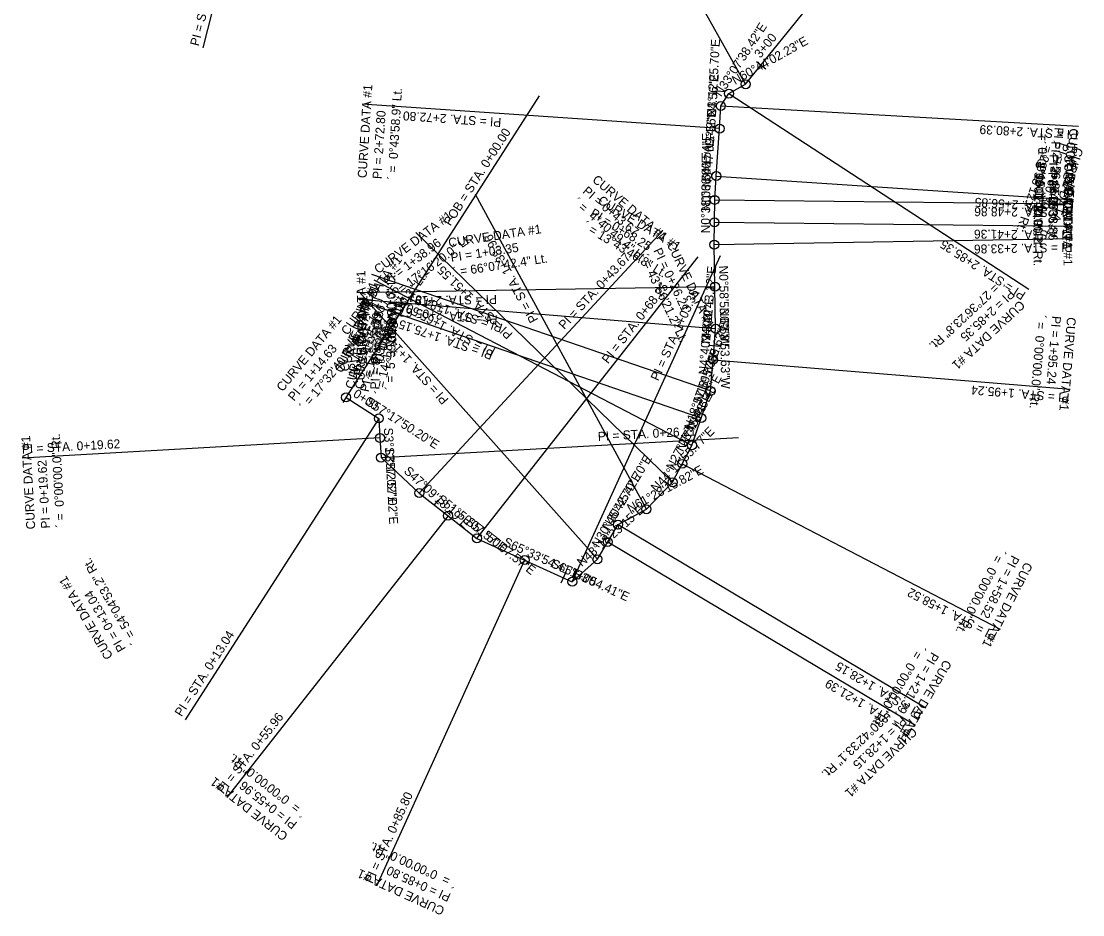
# Model space of a CAD drawing. Extents: x 1158784 to 1165006, y 610007 to 611539.
# Drawn here: x 1163730.4 to 1164086.1, y 610007.4 to 610306.8 of the extents above; entities that cross this region are included whole.
import ezdxf

# ---------------------------------------------------------------- set-up
doc = ezdxf.new("R2010")
doc.units = 0
for name, color, linetype in [('D_Roadway_Centerline', 7, 'Continuous'), ('D_Roadway_Centerline_Bearings', 7, 'Continuous'), ('D_Roadway_Centerline_CurveData', 7, 'Continuous'), ('D_Roadway_Centerline_Flags', 7, 'Continuous'), ('D_Roadway_Centerline_Text', 7, 'Continuous')]:
    doc.layers.add(name, color=color, linetype=linetype)

msp = doc.modelspace()

# ---------------------------------------------------------------- linework, layer by layer
at = {"layer": 'D_Roadway_Centerline'}
for p, q in [((1163973.13, 610285.71), (1164038.5, 610366.61)), ((1163967.54, 610282.58), (1163973.13, 610285.71)), ((1163964.82, 610278.42), (1163967.54, 610282.58)), ((1163964.4, 610270.84), (1163964.82, 610278.42)), ((1163963.3, 610254.93), (1163964.4, 610270.84)), ((1163962.77, 610246.96), (1163963.3, 610254.93)), ((1163962.69, 610239.46), (1163962.77, 610246.96)), ((1163962.61, 610231.96), (1163962.69, 610239.46)), ((1163962.85, 610217.87), (1163962.61, 610231.96)), ((1163963.09, 610203.78), (1163962.85, 610217.87)), ((1163962.24, 610193.38), (1163963.09, 610203.78)), ((1163961.39, 610182.98), (1163962.24, 610193.38)), ((1163958.25, 610173.85), (1163961.39, 610182.98)), ((1163839.27, 610180.8), (1163850.24, 610173.76)), ((1163850.24, 610173.76), (1163850.61, 610167.18)), ((1163955.12, 610164.72), (1163958.25, 610173.85)), ((1163850.61, 610167.18), (1163850.98, 610160.61)), ((1163951.9, 610158.53), (1163955.12, 610164.72)), ((1163850.98, 610160.61), (1163863.78, 610148.74)), ((1163948.68, 610152.34), (1163951.9, 610158.53)), ((1163939.9, 610143.31), (1163948.68, 610152.34)), ((1163863.78, 610148.74), (1163873.45, 610141.14)), ((1163930.41, 610138.15), (1163939.9, 610143.31)), ((1163873.45, 610141.14), (1163883.11, 610133.55)), ((1163926.95, 610132.35), (1163930.41, 610138.15)), ((1163883.11, 610133.55), (1163899.09, 610126.29)), ((1163923.49, 610126.54), (1163926.95, 610132.35)), ((1163899.09, 610126.29), (1163915.06, 610119.03)), ((1163915.06, 610119.03), (1163923.49, 610126.54))]:
    msp.add_line(p, q, dxfattribs=at)
at = {"layer": 'D_Roadway_Centerline_Flags'}
for points in [[(1163820.82, 610414.26), (1163791.31, 610297.95)], [(1163973.13, 610285.71), (1163914.47, 610390.4)], [(1163839.27, 610180.8), (1163904.11, 610281.78)], [(1163967.54, 610282.58), (1164068.03, 610217)], [(1163964.4, 610270.84), (1163844.68, 610279.08)], [(1163964.82, 610278.42), (1164084.63, 610271.7)], [(1163963.3, 610254.93), (1164083.04, 610247.01)], [(1163939.9, 610143.31), (1163882.59, 610248.74)], [(1163962.77, 610246.96), (1164082.77, 610245.63)], [(1163962.69, 610239.46), (1164082.68, 610238.13)], [(1163948.68, 610152.34), (1163862.64, 610236)], [(1163863.78, 610148.74), (1163945.38, 610236.72)], [(1163962.61, 610231.96), (1164082.59, 610234.02)], [(1163883.11, 610133.55), (1163957.26, 610227.9)], [(1163915.06, 610119.03), (1163964.7, 610228.28)], [(1163961.39, 610182.98), (1163847.9, 610221.98)], [(1163962.85, 610217.87), (1163842.87, 610215.81)], [(1163955.12, 610164.72), (1163848.65, 610220.09)], [(1163963.09, 610203.78), (1163843.49, 610213.56)], [(1163923.49, 610126.54), (1163843.67, 610216.14)], [(1163958.25, 610173.85), (1163844.77, 610212.85)], [(1163962.24, 610193.38), (1164081.84, 610183.59)], [(1163850.24, 610173.76), (1163785.41, 610072.78)], [(1163850.61, 610167.18), (1163730.8, 610160.45)], [(1163850.98, 610160.61), (1163970.79, 610167.34)], [(1163951.9, 610158.53), (1164058.36, 610103.16)], [(1163873.45, 610141.14), (1163799.29, 610046.79)], [(1163930.41, 610138.15), (1164033.52, 610076.78)], [(1163926.95, 610132.35), (1164030.07, 610070.97)], [(1163899.09, 610126.29), (1163849.45, 610017.04)]]:
    msp.add_lwpolyline(points, dxfattribs=at)
for centre in [(1163973.13, 610285.71), (1163967.54, 610282.58), (1163964.82, 610278.42), (1163964.4, 610270.84), (1163963.3, 610254.93), (1163962.77, 610246.96), (1163962.69, 610239.46), (1163962.61, 610231.96), (1163962.85, 610217.87), (1163963.09, 610203.78), (1163962.24, 610193.38), (1163839.27, 610180.8), (1163961.39, 610182.98), (1163850.24, 610173.76), (1163958.25, 610173.85), (1163850.61, 610167.18), (1163955.12, 610164.72), (1163850.98, 610160.61), (1163951.9, 610158.53), (1163948.68, 610152.34), (1163863.78, 610148.74), (1163873.45, 610141.14), (1163939.9, 610143.31), (1163930.41, 610138.15), (1163883.11, 610133.55), (1163926.95, 610132.35), (1163899.09, 610126.29), (1163923.49, 610126.54), (1163915.06, 610119.03)]:
    msp.add_circle(centre, 1.5, dxfattribs=at)
at = {"layer": 'D_Roadway_Centerline_Text'}
for points in [[(1163976.75, 610293.37), (1163979.86, 610290.86)], [(1163960.85, 610248.23), (1163962.85, 610248.09)], [(1163960.64, 610198.28), (1163964.62, 610197.96)], [(1163840.35, 610182.49), (1163838.19, 610179.12)], [(1163946.16, 610152.63), (1163947.6, 610151.23)], [(1163870, 610146.4), (1163868.76, 610144.82)], [(1163912.85, 610122.23), (1163911.19, 610118.59)]]:
    msp.add_lwpolyline(points, dxfattribs=at)

# ---------------------------------------------------------------- texts
at = {"layer": 'D_Roadway_Centerline_Bearings'}
for s, rotation, p in [('N33%%d07\'38.42"E', 56.8727, (1163964.92, 610281.32)), ('N3%%d12\'25.70"E', 86.7929, (1163963.11, 610274.71)), ('N60%%d44\'02.23"E', 29.266, (1163969.6, 610285.45)), ('N3%%d56\'24.56"E', 86.0598, (1163962.35, 610262.99)), ('N3%%d47\'09.42"E', 86.214, (1163961.54, 610251.04)), ('N0%%d38\'06.54"E', 89.3648, (1163961.23, 610243.23)), ('N0%%d38\'06.54"E', 89.3648, (1163961.15, 610235.73)), ('N4%%d40\'43.12"E', 85.3214, (1163961.17, 610198.7)), ('N0%%d58\'53.63"W', 270.9816, (1163964.23, 610224.94)), ('N4%%d40\'43.12"E', 85.3214, (1163960.32, 610188.3)), ('N0%%d58\'53.63"W', 270.9816, (1163964.47, 610210.85)), ('N18%%d57\'59.63"E', 71.0334, (1163958.4, 610178.9)), ('N18%%d57\'59.63"E', 71.0334, (1163955.27, 610169.77)), ('N27%%d28\'45.48"E', 62.5207, (1163952.17, 610162.32)), ('N27%%d28\'45.48"E', 62.5207, (1163948.95, 610156.13)), ('S57%%d17\'50.20"E', 327.2973, (1163845.57, 610178.54)), ('S3%%d12\'57.02"E', 273.2158, (1163851.93, 610170.55)), ('N44%%d11\'55.77"E', 45.8012, (1163943.21, 610148.87)), ('S3%%d12\'57.02"E', 273.2158, (1163852.3, 610163.98)), ('N30%%d45\'42.70"E', 59.2381, (1163927.39, 610136.02)), ('S47%%d09\'18.19"E', 317.1551, (1163858.4, 610155.77)), ('N61%%d28\'15.82"E', 28.5289, (1163934.44, 610142.05)), ('N30%%d45\'42.70"E', 59.2381, (1163923.93, 610130.21)), ('S51%%d50\'07.57"E', 321.8354, (1163869.54, 610146.12)), ('N48%%d18\'23.15"E', 41.6936, (1163918.28, 610123.9)), ('S51%%d50\'07.57"E', 321.8354, (1163879.2, 610138.52)), ('S65%%d33\'54.41"E', 335.5651, (1163891.72, 610131.28)), ('S65%%d33\'54.41"E', 335.5651, (1163907.7, 610124.02))]:
    msp.add_text(s, height=3, rotation=rotation, dxfattribs=at).set_placement(p)
at = {"layer": 'D_Roadway_Centerline_CurveData'}
for s, rotation, p in [('CURVE DATA #1', 86.4264, (1163846.13, 610254.18)), ('´ =  0%%d43\'58.9" Lt.', 86.4264, (1163856.11, 610253.56)), ('PI = 2+72.80', 86.4264, (1163851.12, 610253.87)), ('´ =  0%%d09\'15.1" Rt.', 266.1369, (1164071.68, 610271.67)), ('PI = 2+56.85', 266.1369, (1164076.66, 610271.33)), ('CURVE DATA #1', 266.1369, (1164081.65, 610271)), ('´ = 29%%d55\'12.7" Rt.', 251.8328, (1164073.97, 610267.86)), ('´ =  3%%d09\'02.9" Rt.', 267.7894, (1164070.62, 610266.81)), ('PI = 2+80.39', 251.8328, (1164078.72, 610266.3)), ('CURVE DATA #1', 251.8328, (1164083.47, 610264.74)), ('PI = 2+48.86', 267.7894, (1164075.62, 610266.62)), ('CURVE DATA #1', 267.7894, (1164080.61, 610266.43)), ('´ =  0%%d00\'00.0" Rt.', 269.3648, (1164069.95, 610262.27)), ('PI = 2+41.36', 269.3648, (1164074.95, 610262.22)), ('CURVE DATA #1', 269.3648, (1164079.95, 610262.16)), ('´ =  1%%d37\'00.2" Rt.', 270.1732, (1164069.54, 610256.29)), ('PI = 2+33.86', 270.1732, (1164074.54, 610256.3)), ('CURVE DATA #1', 270.1732, (1164079.54, 610256.32)), ('CURVE DATA #1', 319.4952, (1163921.53, 610253.29)), ('PI = 0+43.67', 319.4952, (1163918.28, 610249.48)), ('´ =  4%%d40\'49.4" Lt.', 319.4952, (1163915.03, 610245.68)), ('CURVE DATA #1', 328.7003, (1163923.38, 610245.99)), ('CURVE DATA #1', 37.1651, (1163850.09, 610222.05)), ('PI = 0+68.25', 328.7003, (1163920.79, 610241.72)), ('CURVE DATA #1', 8.6293, (1163873.78, 610231.1)), ('´ = 13%%d43\'46.8" Lt.', 328.7003, (1163918.19, 610237.44)), ('´ = 17%%d16\'20.0" Lt.', 37.1651, (1163856.13, 610214.08)), ('PI = 1+38.96', 37.1651, (1163853.11, 610218.07)), ('PI = 1+03.35', 8.6293, (1163874.53, 610226.16)), ('PI = 0+26.21', 295.1854, (1163942.12, 610229.99)), ('CURVE DATA #1', 295.1854, (1163946.65, 610232.11)), ('CURVE DATA #1', 54.1609, (1163839.78, 610201.39)), ('´ = 66%%d07\'42.4" Lt.', 8.6293, (1163875.28, 610221.22)), ('´ = 43%%d56\'21.2" Lt.', 295.1854, (1163937.6, 610227.86)), ('CURVE DATA #1', 90.9816, (1163846.28, 610191.87)), ('´ = 16%%d43\'10.3" Lt.', 54.1609, (1163847.88, 610195.53)), ('´ =  0%%d00\'00.0" Lt.', 90.9816, (1163856.28, 610192.04)), ('CURVE DATA #1', 66.7771, (1163838.13, 610188.8)), ('CURVE DATA #1', 71.0334, (1163839.8, 610189.18)), ('PI = 1+51.55', 54.1609, (1163843.83, 610198.46)), ('´ = 27%%d36\'23.8" Rt.', 223.0694, (1164058.14, 610220.8)), ('PI = 2+85.35', 223.0694, (1164061.55, 610217.15)), ('CURVE DATA #1', 78.1774, (1163841.95, 610183.46)), ('CURVE DATA #1', 88.1515, (1163845.38, 610183.56)), ('´ =  8%%d30\'45.9" Lt.', 66.7771, (1163847.32, 610184.86)), ('´ =  0%%d00\'00.0" Lt.', 71.0334, (1163849.26, 610185.93)), ('PI = 2+19.77', 90.9816, (1163851.28, 610191.95)), ('´ =  5%%d39\'36.8" Lt.', 88.1515, (1163855.37, 610183.24)), ('PI = 1+75.15', 71.0334, (1163844.53, 610187.55)), ('´ = 14%%d17\'16.5" Lt.', 78.1774, (1163851.74, 610181.41)), ('CURVE DATA #1', 223.0694, (1164064.97, 610213.49)), ('CURVE DATA #1', 50.4659, (1163817.98, 610182.5)), ('PI = 1+65.50', 66.7771, (1163842.73, 610186.83)), ('PI = 2+05.67', 88.1515, (1163850.38, 610183.4)), ('´ =  0%%d00\'00.0" Rt.', 265.3214, (1164070.84, 610208.57)), ('PI = 1+95.24', 265.3214, (1164075.82, 610208.16)), ('CURVE DATA #1', 265.3214, (1164080.81, 610207.75)), ('PI = 1+84.81', 78.1774, (1163846.85, 610182.43)), ('´ = 17%%d32\'40.5" Lt.', 50.4659, (1163825.69, 610176.14)), ('PI = 1+14.63', 50.4659, (1163821.84, 610179.32)), ('CURVE DATA #1', 93.2158, (1163735.15, 610136.66)), ('´ =  0%%d00\'00.0" Rt.', 93.2158, (1163745.13, 610137.22)), ('PI = 0+19.62', 93.2158, (1163740.14, 610136.94)), ('´ =  0%%d00\'00.0" Rt.', 242.5207, (1164057.9, 610130.45)), ('PI = 1+58.52', 242.5207, (1164062.33, 610128.14)), ('´ = 54%%d04\'53.2" Rt.', 120.2566, (1163769.91, 610099.11)), ('CURVE DATA #1', 242.5207, (1164066.77, 610125.84)), ('CURVE DATA #1', 120.2566, (1163761.28, 610094.07)), ('PI = 0+13.04', 120.2566, (1163765.59, 610096.59)), ('´ =  0%%d00\'00.0" Rt.', 239.2381, (1164031.17, 610098.24)), ('CURVE DATA #1', 239.2381, (1164039.76, 610093.13)), ('PI = 1+21.39', 239.2381, (1164035.47, 610095.68)), ('´ = 30%%d42\'33.1" Rt.', 223.8835, (1164021.88, 610077.67)), ('PI = 1+28.15', 223.8835, (1164025.34, 610074.07)), ('CURVE DATA #1', 223.8835, (1164028.81, 610070.46)), ('´ =  0%%d00\'00.0" Rt.', 141.8354, (1163826.2, 610042.18)), ('CURVE DATA #1', 141.8354, (1163820.02, 610034.32)), ('PI = 0+55.96', 141.8354, (1163823.11, 610038.25)), ('´ =  0%%d00\'00.0" Rt.', 155.5651, (1163876.67, 610018.94)), ('CURVE DATA #1', 155.5651, (1163872.54, 610009.84)), ('PI = 0+85.80', 155.5651, (1163874.61, 610014.39))]:
    msp.add_text(s, height=3, rotation=rotation, dxfattribs=at).set_placement(p)
at = {"layer": 'D_Roadway_Centerline_Flags'}
for s, rotation, p in [('PI = STA. 7+03.19', 75.7635, (1163789.86, 610298.31)), ('PI = STA. 2+72.80', 176.0598, (1163891.37, 610274.37)), ('POB = STA. 0+00.00', 57.2973, (1163874.22, 610238.01)), ('PI = STA. 2+80.39', 176.7929, (1164084.55, 610270.21)), ('PI = STA. 2+56.85', 176.214, (1164082.94, 610245.51)), ('PI = STA. 2+48.86', 179.3648, (1164082.75, 610244.13)), ('PI = STA. 1+38.96', 118.5289, (1163903.7, 610206.77)), ('PI = STA. 2+41.36', 179.3648, (1164082.67, 610236.63)), ('PI = STA. 2+85.35', 146.8727, (1164067.21, 610215.74)), ('PI = STA. 2+33.86', 180.9816, (1164082.62, 610232.52)), ('PI = STA. 0+43.67', 47.1551, (1163912.39, 610203.35)), ('PI = STA. 1+51.55', 135.8012, (1163895.32, 610202.14)), ('PI = STA. 0+68.25', 51.8354, (1163927.02, 610191.85)), ('PI = STA. 1+03.35', 65.5651, (1163943.88, 610186.08)), ('PI = STA. 2+19.77', 180.9816, (1163889.79, 610215.12)), ('PI = STA. 1+84.81', 161.0334, (1163891.95, 610205.26)), ('PI = STA. 2+05.67', 175.3214, (1163890.11, 610208.24)), ('PI = STA. 1+65.50', 152.5207, (1163889.57, 610197.12)), ('PI = STA. 1+75.15', 161.0334, (1163888.76, 610196.15)), ('PI = STA. 1+14.63', 131.6936, (1163873.79, 610180.08)), ('PI = STA. 1+95.24', 175.3214, (1164081.72, 610182.09)), ('PI = STA. 0+26.21', 3.2158, (1163923.69, 610166.19)), ('PI = STA. 0+19.62', 3.2158, (1163730.72, 610161.95)), ('PI = STA. 1+58.52', 152.5207, (1164057.66, 610101.83)), ('PI = STA. 0+13.04', 57.2973, (1163784.15, 610073.59)), ('PI = STA. 1+28.15', 149.2381, (1164032.76, 610075.49)), ('PI = STA. 1+21.39', 149.2381, (1164029.3, 610069.68)), ('PI = STA. 0+55.96', 51.8354, (1163798.12, 610047.72)), ('PI = STA. 0+85.80', 65.5651, (1163848.08, 610017.66))]:
    msp.add_text(s, height=3, rotation=rotation, dxfattribs=at).set_placement(p)
at = {"layer": 'D_Roadway_Centerline_Text'}
for s, rotation, p in [('3+00', 51.0616, (1163978.08, 610294.22)), ('2+00', 85.3214, (1163961.26, 610199.74)), ('0+00', 327.2973, (1163841.35, 610181.25)), ('1+00', 335.5651, (1163914, 610121.16))]:
    msp.add_text(s, height=3, rotation=rotation, dxfattribs=at).set_placement(p)

doc.saveas('drawing.dxf')
